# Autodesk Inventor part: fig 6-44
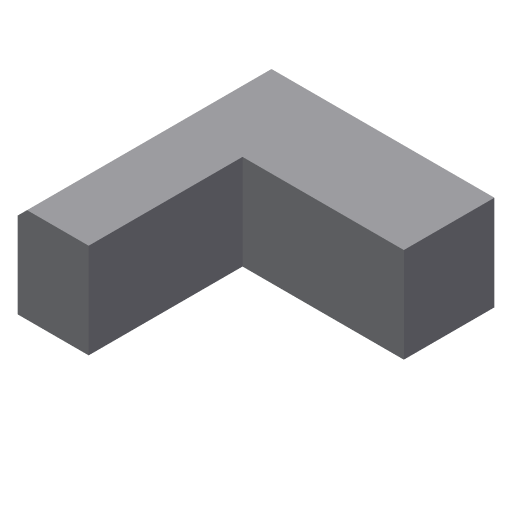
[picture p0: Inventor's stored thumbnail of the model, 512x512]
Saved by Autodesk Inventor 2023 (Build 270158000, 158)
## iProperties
Created: 2010-08
Part Number: fig 6-44
Document SubType Name: Modeling
Designer: CADSoft
Density: 1 g/cm^3
Material: Generic
Appearance: Default
Author: CADSoft
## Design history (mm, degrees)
sketch "Sketch1"
  geometry: L1 (-33.983, 0)-(-48.97, 0); L2 (-48.97, 0)-(-48.97, 51.503); L3 (-48.97, 51.503)-(0, 51.503); L4 (0, 51.503)-(0, 32.411); L5 (-33.983, 0)-(-33.983, 32.411); L6 (-33.983, 32.411)-(0, 32.411); 1 further point
  constraints: 12 end point, 3 parallel, 2 perpendicular, 1 horizontal
extrude "Extrusion1" new body sketch "Sketch1" distance "d0" = 20; taper "d1" = 0 deg
chamfer "Chamfer1" distance "d2" = 2; stored, may be unused: second distance "d3" = 2, angle "d4" = 45 deg
body "Solid1"
